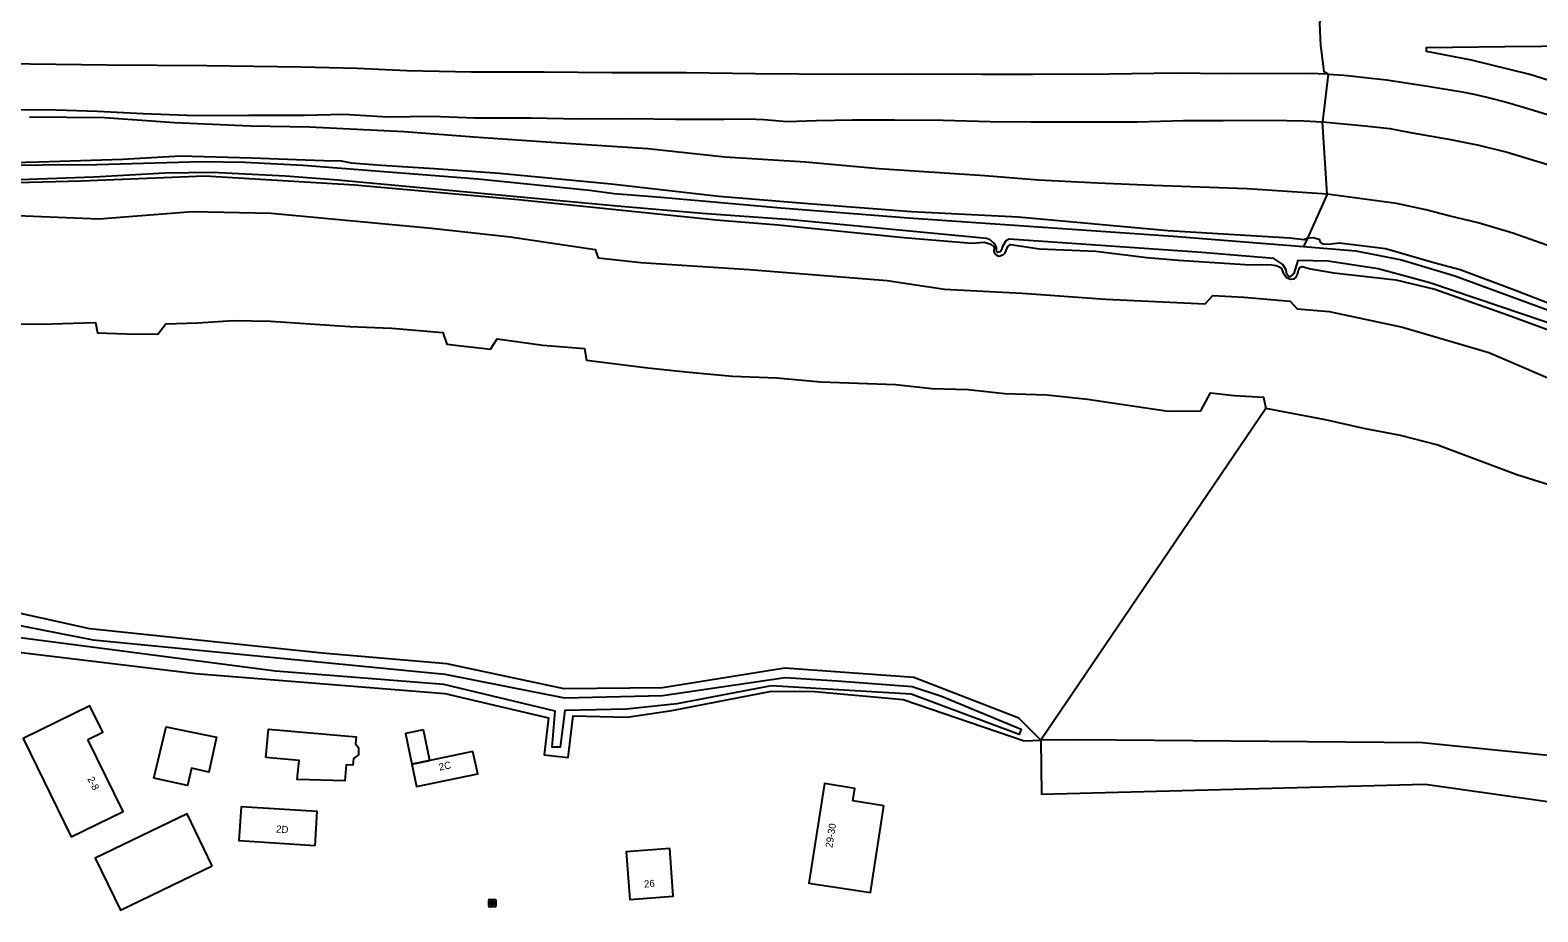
# Model space of a CAD drawing. Extents: x 159451 to 160663, y 388402 to 389723.
# Drawn here: x 160018.5 to 160229.1, y 389501.2 to 389624.4 of the extents above; entities that cross this region are included whole.
import ezdxf

# ---------------------------------------------------------------- set-up
doc = ezdxf.new("R2010")
doc.units = 0
for name, color, linetype in [('IMGEO_Berm_groen', 7, 'Continuous'), ('IMGEO_Grasland_overig', 7, 'Continuous'), ('IMGEO_Greppel_droge_sloot', 7, 'Continuous'), ('IMGEO_Groenvoorziening', 7, 'Continuous'), ('IMGEO_Loofbos', 7, 'Continuous'), ('IMGEO_Oever', 7, 'Continuous'), ('IMGEO_Pand', 7, 'Continuous'), ('IMGEO_Pand_nummerreeks', 7, 'Continuous'), ('IMGEO_Pand_overbouw', 7, 'Continuous'), ('IMGEO_Pand_vergunning_verleend', 7, 'Continuous'), ('IMGEO_Rijbaan_autosnelweg', 7, 'Continuous'), ('IMGEO_Rioolput', 7, 'Continuous'), ('IMGEO_Voetpad_open', 7, 'Continuous'), ('IMGEO_Waterloop', 7, 'Continuous')]:
    doc.layers.add(name, color=color, linetype=linetype)

msp = doc.modelspace()

# ---------------------------------------------------------------- linework, layer by layer
at = {"layer": 'IMGEO_Berm_groen'}
for points in [[(160199.83, 389618.29), (160199.06, 389611.64)], [(160015.39, 389613.34), (160022.16, 389613.3), (160027.95, 389613.1), (160034.3, 389612.79), (160041.67, 389612.53), (160049.05, 389612.57), (160056.87, 389612.57), (160062.34, 389612.68), (160068.51, 389612.33), (160074.69, 389612.41), (160080.58, 389612.18), (160088.46, 389612.16), (160095.33, 389612.03), (160102.59, 389612.1), (160108.66, 389611.98), (160115.44, 389611.98), (160118.72, 389612.04), (160121.07, 389611.96), (160124.21, 389611.67), (160128.36, 389611.83), (160133.38, 389611.9), (160139.29, 389611.88), (160146.05, 389611.84), (160152.63, 389611.67), (160158.3, 389611.64), (160167.51, 389611.64), (160173.2, 389611.63), (160179.63, 389611.82), (160185.19, 389611.83), (160191.71, 389611.86), (160196.47, 389611.77), (160199.06, 389611.64)], [(160199.73, 389601.52), (160188.52, 389602.28), (160175.38, 389602.74), (160167.63, 389603.07), (160159.39, 389603.47), (160151.89, 389604.1), (160137.08, 389605.05), (160126.83, 389605.98), (160115.57, 389606.67), (160104.79, 389607.83), (160091.96, 389608.71), (160080.5, 389609.47), (160070.78, 389610.22), (160057.54, 389610.87), (160049.3, 389611.01), (160038.68, 389611.48), (160028.89, 389612.16), (160018.44, 389612.27)], [(160199.06, 389611.64), (160204.97, 389611.08), (160208.44, 389610.67), (160211.33, 389610.14), (160216.92, 389609.14), (160220.88, 389608.35), (160224.85, 389607.4), (160232.06, 389605.21)], [(160196.95, 389595.36), (160196.5, 389595.12), (160194.49, 389595.38), (160177.5, 389596.37), (160156.52, 389598.28), (160141.66, 389599.05), (160127.79, 389600.11), (160114.73, 389601.17), (160099.67, 389602.91), (160084.08, 389604.39), (160074.96, 389605.04), (160067.61, 389605.52), (160063.39, 389605.86), (160062.01, 389606.13), (160059.48, 389606.18), (160049.45, 389606.54), (160039.47, 389606.81), (160031.48, 389606.35), (160019.74, 389605.99), (160008.56, 389605.71), (159999.81, 389605.41), (159994.98, 389605.68), (159989.35, 389606.49)], [(160199.73, 389601.52), (160196.95, 389595.36)], [(160233.58, 389593.29), (160225.64, 389596.05), (160220.78, 389597.49), (160216.89, 389598.44), (160213.47, 389599.33), (160209.38, 389600.22), (160199.73, 389601.52)], [(160196.95, 389595.36), (160197.77, 389595.45), (160198.6, 389595.22), (160198.71, 389594.8), (160199.04, 389594.59), (160199.83, 389594.55), (160201.43, 389594.7), (160207.86, 389593.92), (160214.63, 389591.97), (160218.29, 389591.01), (160225.89, 389588.14), (160233.69, 389585.1)]]:
    msp.add_lwpolyline(points, dxfattribs=at)
at = {"layer": 'IMGEO_Grasland_overig'}
msp.add_lwpolyline([(160199.73, 389601.52), (160199.06, 389611.64)], dxfattribs=at)
at = {"layer": 'IMGEO_Greppel_droge_sloot'}
for points in [[(160236.48, 389581.54), (160214.07, 389589.12), (160206.82, 389591.07), (160199.81, 389592.14), (160195.59, 389592.24), (160195.04, 389590.41), (160194.84, 389590.16), (160194.5, 389589.98), (160194.32, 389590.03), (160194.07, 389590.33), (160193.96, 389590.93), (160193.51, 389591.71), (160192.26, 389592.52), (160182.18, 389593.36), (160155.29, 389595.23), (160154.82, 389594.98), (160154.32, 389594.13), (160154.23, 389593.71), (160154.05, 389593.48), (160153.64, 389593.36), (160153.53, 389593.57), (160153.53, 389594.06), (160153.17, 389594.64), (160152.63, 389595.13), (160152.1, 389595.32), (160124.84, 389597.92), (160112.39, 389598.82), (160100.54, 389599.83), (160061.51, 389603.47), (160054.19, 389604.02), (160043.96, 389604.53), (160037.4, 389604.44), (160027.4, 389603.87), (160001.54, 389602.95)], [(160012.45, 389605.55), (160027.83, 389605.66), (160042.51, 389606.1), (160048.5, 389605.98), (160056.66, 389605.56), (160081.04, 389603.68), (160096.67, 389602.06), (160100.11, 389601.61), (160106.61, 389601.11), (160123.41, 389599.62), (160141.23, 389598.21), (160178.21, 389595.65), (160196.42, 389594.19)], [(160196.42, 389594.19), (160203.71, 389593.61), (160210.08, 389592.33), (160217.52, 389590.11), (160249.39, 389578.41)]]:
    msp.add_lwpolyline(points, dxfattribs=at)
at = {"layer": 'IMGEO_Groenvoorziening'}
for points in [[(160012.97, 389603.03), (160025.66, 389603.4), (160042.91, 389604.06), (160063.89, 389602.81), (160086.72, 389600.79), (160114.34, 389597.95), (160123, 389597.22), (160140.59, 389595.45), (160150.07, 389594.68), (160151.77, 389594.8), (160152.74, 389594.54), (160153.2, 389594.1), (160153.16, 389593.46), (160153.28, 389593.18), (160153.5, 389592.97), (160153.89, 389592.85), (160154.49, 389593.07), (160154.71, 389593.32), (160155.1, 389594.2), (160155.45, 389594.47), (160159.5, 389593.87), (160167.37, 389593.53), (160174.51, 389592.68), (160178.96, 389592.3), (160188.27, 389591.71), (160191.94, 389591.62), (160192.59, 389591.54), (160193.02, 389591.36), (160193.31, 389591.13), (160193.57, 389590.51), (160194.01, 389589.86), (160194.57, 389589.63), (160195.11, 389589.7), (160195.37, 389589.93), (160195.57, 389590.31), (160195.7, 389590.89), (160195.94, 389591.32), (160196.22, 389591.42), (160197.36, 389591.08), (160200.62, 389590.51), (160209.28, 389589.53), (160214.73, 389588.25), (160224.89, 389584.64), (160238.72, 389579.56)], [(160191.12, 389571.55), (160159.71, 389525.23)], [(160159.71, 389525.23), (160156.63, 389528.31), (160141.97, 389533.98), (160123.96, 389535.27), (160106.88, 389532.52), (160093.1, 389532.4), (160076.74, 389535.9), (160059.3, 389537.37), (160026.85, 389540.77), (160013.37, 389543.74)], [(160012.22, 389538.08), (160041.63, 389534.55), (160076.45, 389531.72), (160090.94, 389528.33), (160090.33, 389523.17), (160093.68, 389522.77), (160094.37, 389528.6), (160101.92, 389528.44), (160108.14, 389529.34), (160122.1, 389532.06), (160128.13, 389532), (160140.5, 389530.91), (160157.4, 389525.1), (160159.71, 389525.23)]]:
    msp.add_lwpolyline(points, dxfattribs=at)
at = {"layer": 'IMGEO_Loofbos'}
for points in [[(160003.99, 389599.03), (160028.14, 389598.05), (160041.14, 389599.09), (160052.17, 389598.86), (160074.61, 389596.77), (160085.57, 389595.57), (160097.43, 389593.79), (160097.88, 389592.6), (160103.82, 389591.95), (160118.96, 389591), (160138.24, 389589.43), (160146.25, 389588.26), (160157.11, 389587.69), (160168.81, 389586.82), (160182.65, 389586.18), (160183.73, 389587.35), (160188.07, 389587.13), (160194.56, 389586.58), (160195.52, 389585.5), (160199.98, 389585.11), (160210.22, 389582.92), (160222.31, 389579.37), (160233.48, 389574.57)], [(160015.25, 389583.33), (160021.51, 389583.38), (160027.66, 389583.58), (160027.95, 389582.16), (160031.96, 389581.98), (160036.37, 389581.95), (160037.49, 389583.38), (160041.95, 389583.55), (160046.91, 389583.87), (160052.11, 389583.77), (160063.19, 389583.02), (160069, 389582.78), (160076.19, 389582.19), (160076.73, 389580.55), (160082.84, 389579.84), (160083.75, 389581.3), (160090.14, 389580.43), (160095.94, 389579.94), (160096.25, 389578.33), (160104.83, 389577.24), (160110.58, 389576.62), (160116.63, 389576.09), (160122.81, 389575.86), (160128.97, 389575.28), (160139.4, 389574.9), (160144.48, 389574.34), (160149.58, 389574.23), (160154.7, 389573.65), (160160.55, 389573.46), (160166.21, 389572.87), (160177.5, 389571.17), (160182.05, 389571.24), (160183.42, 389573.77), (160186.71, 389573.4), (160190.8, 389573.13), (160191.12, 389571.55)], [(160237.78, 389558.66), (160226.18, 389562.3), (160215.01, 389566.48), (160209.97, 389567.79), (160204.81, 389568.79), (160199.48, 389569.98), (160191.12, 389571.55)]]:
    msp.add_lwpolyline(points, dxfattribs=at)
at = {"layer": 'IMGEO_Oever'}
msp.add_lwpolyline([(160196.95, 389595.36), (160196.42, 389594.19)], dxfattribs=at)
at = {"layer": 'IMGEO_Pand'}
for points in [[(160026.58, 389525.29), (160028.69, 389526.32), (160026.88, 389530.02), (160017.55, 389525.44), (160024.27, 389511.69), (160031.52, 389515.23), (160026.58, 389525.29)], [(160080.37, 389523.63), (160074.34, 389522.38), (160071.85, 389521.86), (160072.49, 389518.74), (160081.04, 389520.52), (160080.37, 389523.63)], [(160137.76, 389516.06), (160133.46, 389516.72), (160133.73, 389518.47), (160129.47, 389519.14), (160127.3, 389505.22), (160135.92, 389503.91), (160137.76, 389516.06)], [(160058.28, 389510.46), (160047.72, 389511.16), (160048.03, 389515.95), (160058.57, 389515.28), (160058.28, 389510.46)], [(160043.96, 389507.64), (160040.45, 389514.92), (160027.61, 389508.73), (160031.13, 389501.44), (160043.96, 389507.64)], [(160107.87, 389510.07), (160101.8, 389509.61), (160102.3, 389502.95), (160108.36, 389503.42), (160107.87, 389510.07)]]:
    msp.add_lwpolyline(points, dxfattribs=at)
at = {"layer": 'IMGEO_Pand_overbouw'}
msp.add_lwpolyline([(160073.45, 389526.66), (160070.97, 389526.14), (160071.85, 389521.86), (160074.34, 389522.38)], close=True, dxfattribs=at)
at = {"layer": 'IMGEO_Pand_vergunning_verleend'}
for points in [[(160035.81, 389519.91), (160037.54, 389527.09), (160044.57, 389525.62), (160043.48, 389520.75), (160041.05, 389521.29), (160040.51, 389518.86), (160035.81, 389519.91)], [(160051.45, 389522.81), (160051.81, 389526.76), (160064.05, 389525.66), (160063.99, 389524.72), (160064.4, 389524.18), (160064.38, 389523.18), (160063.71, 389522.64), (160063.62, 389521.7), (160062.68, 389521.79), (160062.46, 389519.51), (160055.84, 389519.71), (160056.08, 389522.38), (160051.45, 389522.81)]]:
    msp.add_lwpolyline(points, dxfattribs=at)
at = {"layer": 'IMGEO_Rijbaan_autosnelweg'}
for points in [[(160201.38, 389629.1), (160199.94, 389628.69), (160198.64, 389625.47), (160198.78, 389622.23), (160198.8, 389621.95), (160199.24, 389618.67), (160199.83, 389618.29)], [(160236.46, 389615.58), (160228, 389618.23), (160219.88, 389620.25), (160213.6, 389621.45), (160213.59, 389621.99), (160224.53, 389622.17), (160240.03, 389622.31)], [(160199.83, 389618.29), (160197.07, 389618.36), (160185.36, 389618.33), (160178.63, 389618.41), (160169.26, 389618.27), (160158.61, 389618.24), (160151.57, 389618.26), (160141.38, 389618.29), (160132, 389618.26), (160119.87, 389618.34), (160110.15, 389618.45), (160099.78, 389618.48), (160090.35, 389618.57), (160080.17, 389618.58), (160071.16, 389618.76), (160064.19, 389619.08), (160056.35, 389619.26), (160043.2, 389619.43), (160029.29, 389619.55), (160018.54, 389619.67), (160006.07, 389619.77)], [(160199.83, 389618.29), (160202.1, 389618.13), (160204.59, 389617.88), (160208, 389617.49), (160213.79, 389616.59), (160218.57, 389615.8), (160220.44, 389615.42), (160222.19, 389615.03), (160224.76, 389614.35), (160228.52, 389613.24), (160232.56, 389612.01)]]:
    msp.add_lwpolyline(points, dxfattribs=at)
at = {"layer": 'IMGEO_Rioolput'}
for p, q in [((160082.59, 389502.02), (160082.59, 389502.87)), ((160082.67, 389502.94), (160083.52, 389502.94)), ((160083.52, 389501.94), (160082.67, 389501.94)), ((160083.08, 389502.72), (160083.11, 389502.72)), ((160083.1, 389502.16), (160083.08, 389502.16)), ((160083.59, 389502.87), (160083.59, 389502.02))]:
    msp.add_line(p, q, dxfattribs=at)
for points in [[(160082.59, 389502.02), (160082.59, 389502.87)], [(160082.67, 389502.94), (160083.52, 389502.94)], [(160083.52, 389501.94), (160082.67, 389501.94)], [(160083.18, 389502.64), (160082.93, 389502.64), (160082.93, 389502.24)], [(160082.93, 389502.24), (160083.05, 389502.24), (160083.05, 389502.41), (160083.06, 389502.41)], [(160083.11, 389502.56), (160083.05, 389502.56), (160083.05, 389502.48)], [(160083.05, 389502.48), (160083.1, 389502.48)], [(160083.11, 389502.38), (160083.18, 389502.24), (160083.32, 389502.24), (160083.26, 389502.37)], [(160083.59, 389502.87), (160083.59, 389502.02)]]:
    msp.add_lwpolyline(points, dxfattribs=at)
for centre, radius, start, end in [((160082.67, 389502.87), 0.0765, 91.552, 178.448), ((160082.67, 389502.87), 0.0765, 91.552, 178.448), ((160082.67, 389502.02), 0.0765, 181.552, 268.448), ((160082.67, 389502.02), 0.0765, 181.552, 268.448), ((160083.06, 389502.35), 0.0533, 26.0293, 88.6989), ((160083.09, 389502.67), 0.19, 274.7715, 282.9687), ((160083.11, 389502.47), 0.0964, 77.0061, 93.1865), ((160083.13, 389502.52), 0.0378, 276.6634, 79.6772), ((160083.18, 389502.53), 0.109, 350.3612, 89.416), ((160083.18, 389502.53), 0.112, 277.5842, 350.9817), ((160083.16, 389502.32), 0.108, 29.5134, 73.7905), ((160083.52, 389502.87), 0.0765, 1.552, 88.448), ((160083.52, 389502.87), 0.0765, 1.552, 88.448), ((160083.52, 389502.02), 0.0765, 271.552, 358.448), ((160083.52, 389502.02), 0.0765, 271.552, 358.448)]:
    msp.add_arc(centre, radius, start, end, dxfattribs=at)
for centre, major_axis, ratio, start_param, end_param in [((160083.08, 389502.44), (-0.387, 0.002), 0.722429, 4.712389, 7.853982), ((160083.1, 389502.44), (-0.39, 0.002), 0.717154, 1.570796, 4.712389)]:
    msp.add_ellipse(centre, major_axis=major_axis, ratio=ratio, start_param=start_param, end_param=end_param, dxfattribs=at)
at = {"layer": 'IMGEO_Voetpad_open'}
for points in [[(160491.45, 389579.98), (160463.34, 389565.62), (160450.65, 389560.23), (160437.38, 389558.27), (160424.25, 389555.01), (160416.84, 389550.74), (160408.17, 389541.3), (160398.18, 389520.4), (160392.44, 389513.68), (160387.7, 389510.08), (160381.22, 389508.86), (160373.24, 389508.47), (160330.25, 389514.87), (160288.33, 389517.26), (160213.01, 389524.85), (160164.89, 389525.24), (160159.71, 389525.23)], [(160159.71, 389525.23), (160159.78, 389517.67), (160213.4, 389519.05), (160359.11, 389498.45), (160365.79, 389497.5), (160376.55, 389495.98), (160386.54, 389496.1), (160393.61, 389498.23), (160400, 389502.27), (160405.5, 389509.12), (160410.4, 389517.69), (160412.55, 389528.89), (160414.23, 389535.28), (160420.07, 389541.8), (160428.15, 389546.06), (160437.75, 389548.31), (160443.39, 389548.82), (160453.33, 389551.39), (160465.31, 389557.48), (160487.54, 389570.96)]]:
    msp.add_lwpolyline(points, dxfattribs=at)
at = {"layer": 'IMGEO_Waterloop'}
msp.add_lwpolyline([(160013.05, 389542.02), (160027.34, 389539.24), (160076.46, 389534.42), (160093.15, 389531.13), (160106.86, 389531.48), (160124, 389533.99), (160131.26, 389533.49), (160141.73, 389532.72), (160145.82, 389531.36), (160156.96, 389526.73), (160156.68, 389526.02), (160141.58, 389531.66), (160122.02, 389532.8), (160108.87, 389530.29), (160101.81, 389529.55), (160093.23, 389529.36), (160092.58, 389524.23), (160091.46, 389524.26), (160091.88, 389529.28), (160076.32, 389532.99), (160052.78, 389534.86), (160013.5, 389540)], dxfattribs=at)

# ---------------------------------------------------------------- texts
at = {"layer": 'IMGEO_Pand_nummerreeks'}
for s, rotation, p in [('2C', 11.7514, (160075.73, 389520.95)), ('2-8', 296.1209, (160026.48, 389519.83)), ('29-30', 81.1251, (160130.59, 389510.12)), ('2D', 356.2013, (160052.86, 389512.32)), ('26', 4.4576, (160104.32, 389504.61))]:
    msp.add_text(s, height=1, rotation=rotation, dxfattribs=at).set_placement(p)

doc.saveas('drawing.dxf')
